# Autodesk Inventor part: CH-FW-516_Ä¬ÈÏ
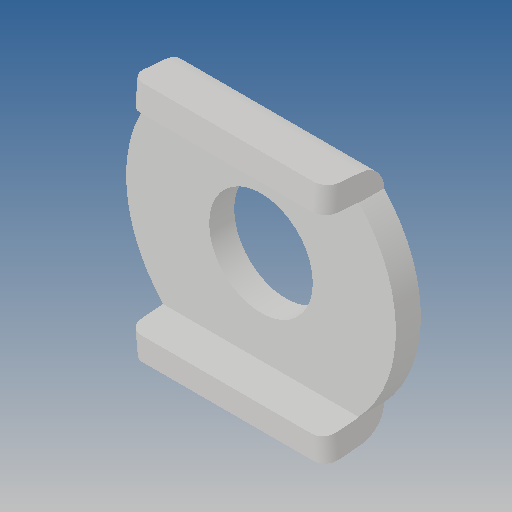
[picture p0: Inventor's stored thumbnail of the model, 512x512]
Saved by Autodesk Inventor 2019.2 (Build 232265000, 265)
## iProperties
Created: 2010-06
Part Number: CH-FW-516_Ä¬ÈÏ
Material: Ogólny
Document SubType Name: Modeling
Designer: CADENGINEERING4
Density: 1 g/cm^3
Appearance: Domyślna
Author: CADENGINEERING4
Revision Number: ÈÎºÎ
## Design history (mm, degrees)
feature "NONE"
node "Bryła1"
